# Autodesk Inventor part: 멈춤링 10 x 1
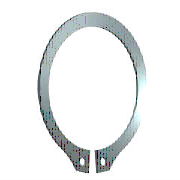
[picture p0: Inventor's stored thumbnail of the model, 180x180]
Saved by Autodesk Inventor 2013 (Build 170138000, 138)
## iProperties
IsCustomPart: 0
Created: 2021-07
Part Number: 멈춤링 10 x 1
Material: 강철, 연강
Description: 리테이닝 링(C형)
Document SubType Name: Modeling
Standard: KS B 1336
Designer: mdu
Standards Organization: KS
Language: ko-KR
Size Designation: 10 x 1
Categories: <MemberInstance><Categories><Category DisplayName="샤프트 부품" InternalName="7f7aeb1f-a693-4053-b835-cee3144e0d98" Mnemonic="SHFT"><Category DisplayName="써클립" Inter
Density: 7.86 g/cm^3
Mass: 0.423084 g
Surface Area: 1.9243 cm^2
Volume: 0.0538275 cm^3
Author: mdu
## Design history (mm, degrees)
sketch "스케치1"
  geometry: L1 (-6, 0)-(6, 0) reference; L2 (0, 20.189)-(0, -80.536) reference; L3 (-48.09, 0)-(48.09, 0) reference; L4 (-0.3, -9.791)-(-0.3, -12.791); L5 (-0.3, -6.54)-(-0.3, -13.29); L6 (-2.795, 1.6)-(3.672, 1.6); L7 (0.3, -6.54)-(0.3, -13.29); L8 (0.3, -9.791)-(0.3, -12.791); C1 r 0.6 at (-1.2, -11.486); C2 r 0.6 at (1.2, -11.486); A1 r 4.8 centre (0, -5) between (0.3, -9.791) and (-0.3, -9.791); A2 r 6.2 centre (0, -4.6) between (2.988, -10.033) and (-2.988, -10.033); A3 r 7.796 centre (0, -5) between (-1.418, -12.666) and (-0.3, -12.791); A4 r 1.2 centre (-1.2, -11.486) between (-2.383, -11.285) and (-1.418, -12.666); A5 r 1.2 centre (-3.566, -11.084) between (-2.383, -11.285) and (-2.988, -10.033); A6 r 1.2 centre (3.566, -11.084) between (2.988, -10.033) and (2.383, -11.285); A7 r 1.2 centre (1.2, -11.486) between (1.418, -12.666) and (2.383, -11.285); A8 r 7.796 centre (0, -5) between (0.3, -12.791) and (1.418, -12.666)
  constraints: 16 point on circle, 12 end point, 10 centre point, 9 symmetric about line, 5 point on line, 4 tangent, 3 coincident, 2 horizontal, 1 perpendicular, 1 vertical, 5 other
  dimensions: "d0" = 9.6 diameter of A1 (= ND); "d1" = 3 distance of L4.end L4.start (= SRB2); "d6" = 0.3 distance between parallel lines of L2 L5 (= 0.25 x SD5); "d7" = 1.6 distance between parallel lines of L6 L3 (= SRB1); "d8" = 0.4 distance of A1.centre A2.centre (= 0.25 x SRB1); "d9" = 1.2 radius of A4 (= SD5); "d10" = 1.2 radius of A5 (= SD5); "d11" = 0.9 distance from line of L4 A4.centre (= 0.75 x SD5); "d12" = 1.2 diameter of C1 (= SD5); "d13" = 1.2 diameter of C2 (= SD5); "d14" = 5 distance from line of A1.centre L1 (= 0.5 x WD)
extrude "본체" new body sketch "스케치1" distance "d2" = 1 (= SD); taper "d3" = 0 deg
workaxis "Work Axis1"
workplane "Work Plane1"
body "Solid1"
other parameters: "SD" = 1 [user parameter; used in 1 equation term], "SRB1" = 1.6 [user parameter; used in 2 equation terms], "ND" = 9.6 [user parameter; used in 1 equation term], "SRB2" = 3 [user parameter; used in 1 equation term], "SD5" = 1.2 [user parameter; used in 6 equation terms], "d15" = 0, "d16" = 0, "d17" = 0, "d41" = 0, "d42" = 0, "SD3" = 9.3 [user parameter], "WDMAX" = 11 [user parameter]
